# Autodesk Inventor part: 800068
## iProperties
Created: 2007-11
Part Number: 800068
Document SubType Name: Modeling
Designer: TH
Density: 8.08 g/cm^3
Mass: 11.8468 g
Surface Area: 11.3549 cm^2
Volume: 1.46619 cm^3
Material: Stainless Steel
Description: N34 NUT M12
Component Category: Fasteners
Author: TH
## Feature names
1. Extrusion1
2. Extrusion2
3. Fillet1
